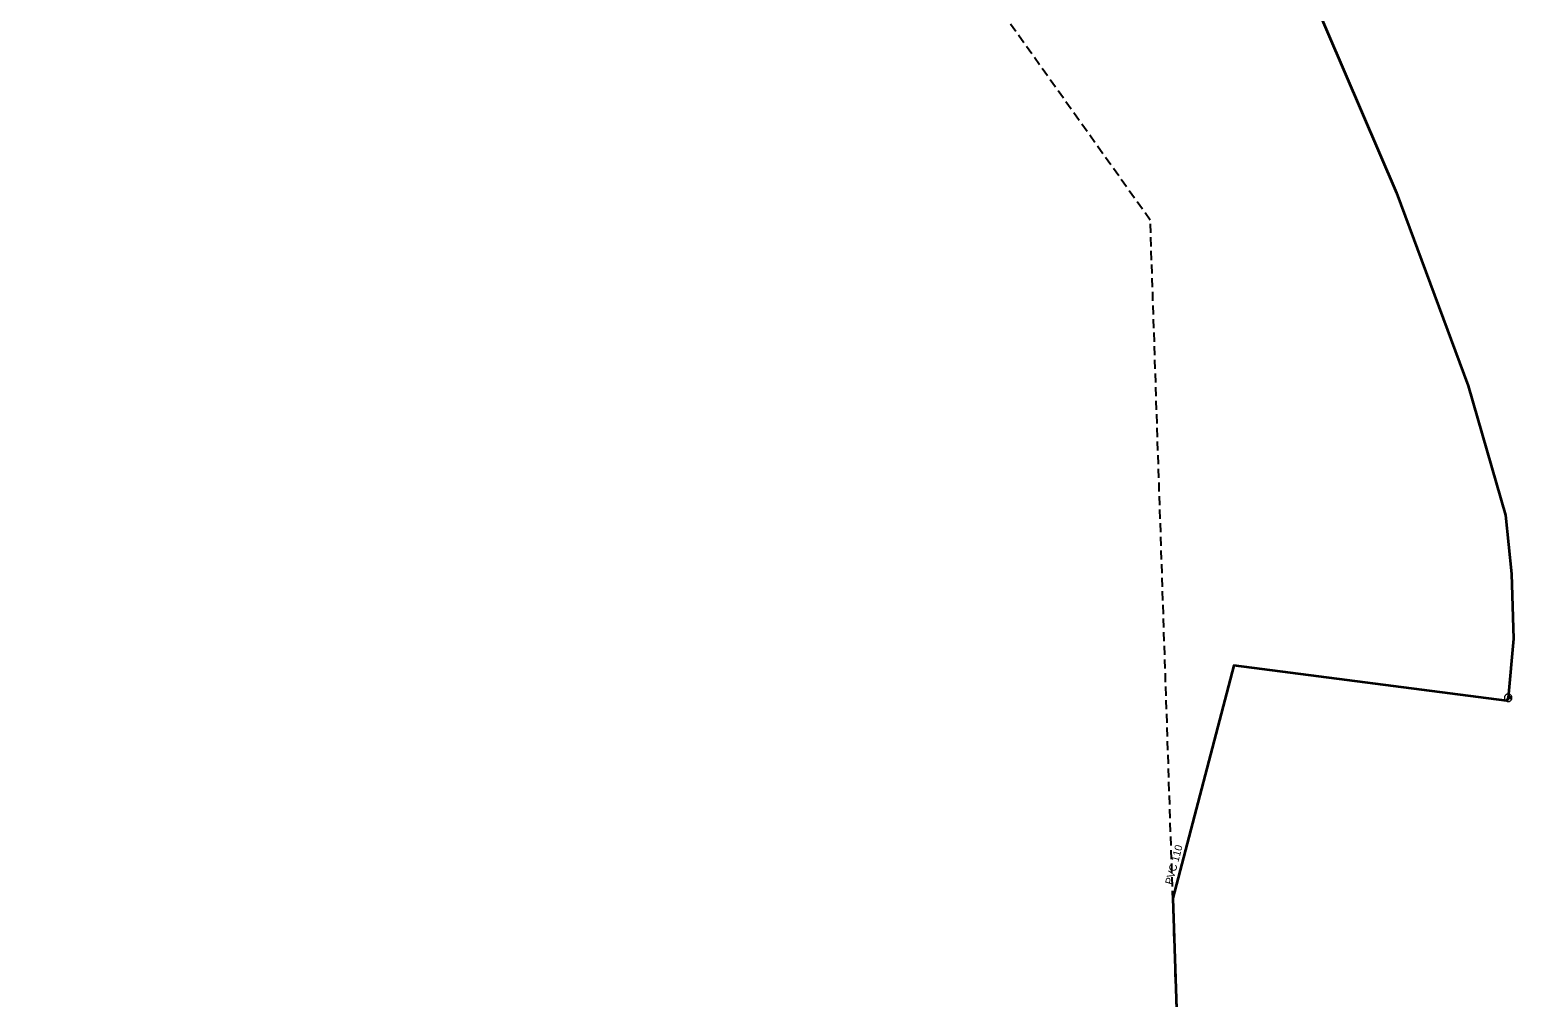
# Model space of a CAD drawing. Extents: x -724334 to -723692, y -972150 to -970648.
# Drawn here: x -724012.8 to -723813.6, y -971527.1 to -971399.3 of the extents above; entities that cross this region are included whole.
import ezdxf

# ---------------------------------------------------------------- set-up
doc = ezdxf.new("R2010")
doc.units = 0
doc.header["$LTSCALE"] = 0.4
doc.linetypes.add('MEDIUM_DASHED', pattern=[4.5, 3, -1.5])
for name, color, linetype, lineweight in [('1', 7, 'Continuous', 25), ('14', 7, 'Continuous', 25), ('17', 7, 'Continuous', 35), ('47', 7, 'Continuous', 13), ('9', 7, 'Continuous', 13)]:
    doc.layers.add(name, color=color, linetype=linetype, lineweight=lineweight)

msp = doc.modelspace()

# ---------------------------------------------------------------- linework, layer by layer
at = {"layer": '1', "linetype": 'MEDIUM_DASHED'}
msp.add_lwpolyline([(-723848.074, -970648.428), (-723714.095, -970720.999), (-724065.788, -971064.318), (-723792.249, -971201.088), (-723702.93, -971508.122), (-723691.766, -972150.101), (-723842.491, -972097.068), (-723864.821, -971424.385), (-723982.052, -971259.703), (-724333.745, -971117.352)], close=True, dxfattribs=at)
at = {"layer": '14', "lineweight": 13}
msp.add_line((-723817.559, -971487.479), (-723817.31, -971487.459), dxfattribs=at)
at = {"layer": '17'}
for points in [[(-723897.32, -971301.379), (-723897.12, -971301.809), (-723878.899, -971335.289), (-723856.64, -971370.239), (-723846.059, -971388.75), (-723832.309, -971420.76), (-723822.829, -971446.28), (-723817.91, -971463.35), (-723817.129, -971471.1), (-723816.85, -971479.71), (-723817.559, -971487.479)], [(-723817.559, -971487.479), (-723817.73, -971487.899), (-723853.789, -971483.199), (-723861.847, -971513.967), (-723856.42, -971677.472)]]:
    msp.add_lwpolyline(points, dxfattribs=at)
at = {"layer": '47'}
for points in [[(-723817.537, -971487.978), (-723817.485, -971487.973), (-723817.434, -971487.963), (-723817.384, -971487.947), (-723817.336, -971487.926), (-723817.29, -971487.9), (-723817.248, -971487.87), (-723817.209, -971487.835), (-723817.174, -971487.796), (-723817.142, -971487.755), (-723817.115, -971487.71), (-723817.093, -971487.662), (-723817.077, -971487.612), (-723817.066, -971487.562), (-723817.06, -971487.509), (-723817.059, -971487.457), (-723817.064, -971487.405), (-723817.074, -971487.354), (-723817.091, -971487.303), (-723817.111, -971487.256), (-723817.137, -971487.21), (-723817.167, -971487.168), (-723817.202, -971487.128), (-723817.241, -971487.093), (-723817.282, -971487.061), (-723817.327, -971487.035), (-723817.375, -971487.013), (-723817.425, -971486.996), (-723817.475, -971486.986), (-723817.528, -971486.98), (-723817.58, -971486.979), (-723817.632, -971486.984), (-723817.683, -971486.994), (-723817.734, -971487.01), (-723817.781, -971487.031), (-723817.827, -971487.057), (-723817.869, -971487.086), (-723817.909, -971487.121), (-723817.944, -971487.16), (-723817.976, -971487.202), (-723818.002, -971487.247), (-723818.024, -971487.295), (-723818.041, -971487.344), (-723818.051, -971487.395), (-723818.057, -971487.448), (-723818.058, -971487.5), (-723818.053, -971487.552), (-723818.043, -971487.603), (-723818.028, -971487.653), (-723818.006, -971487.701), (-723817.98, -971487.747), (-723817.951, -971487.789), (-723817.916, -971487.828), (-723817.877, -971487.863), (-723817.835, -971487.895), (-723817.79, -971487.922), (-723817.742, -971487.944), (-723817.693, -971487.96), (-723817.642, -971487.971), (-723817.589, -971487.977)], [(-723817.555, -971487.56), (-723817.546, -971487.56), (-723817.538, -971487.558), (-723817.53, -971487.555), (-723817.522, -971487.552), (-723817.515, -971487.548), (-723817.508, -971487.542), (-723817.501, -971487.537), (-723817.495, -971487.531), (-723817.491, -971487.524), (-723817.486, -971487.516), (-723817.482, -971487.508), (-723817.48, -971487.5), (-723817.478, -971487.492), (-723817.476, -971487.484), (-723817.477, -971487.475), (-723817.477, -971487.466), (-723817.479, -971487.458), (-723817.482, -971487.45), (-723817.485, -971487.442), (-723817.489, -971487.435), (-723817.495, -971487.428), (-723817.5, -971487.421), (-723817.506, -971487.415), (-723817.513, -971487.41), (-723817.521, -971487.406), (-723817.529, -971487.402), (-723817.537, -971487.4), (-723817.545, -971487.398), (-723817.553, -971487.396), (-723817.562, -971487.397), (-723817.571, -971487.397), (-723817.579, -971487.399), (-723817.587, -971487.402), (-723817.595, -971487.405), (-723817.602, -971487.409), (-723817.609, -971487.414), (-723817.616, -971487.42), (-723817.622, -971487.426), (-723817.627, -971487.433), (-723817.631, -971487.441), (-723817.635, -971487.449), (-723817.637, -971487.457), (-723817.639, -971487.465), (-723817.641, -971487.473), (-723817.64, -971487.482), (-723817.64, -971487.491), (-723817.638, -971487.499), (-723817.635, -971487.507), (-723817.632, -971487.515), (-723817.628, -971487.522), (-723817.623, -971487.529), (-723817.617, -971487.536), (-723817.611, -971487.542), (-723817.604, -971487.546), (-723817.596, -971487.551), (-723817.588, -971487.555), (-723817.58, -971487.557), (-723817.572, -971487.559), (-723817.564, -971487.561)]]:
    msp.add_lwpolyline(points, close=True, dxfattribs=at)
at = {"layer": '9'}
for points in [[(-723817.436, -971487.459), (-723817.436, -971487.472), (-723817.434, -971487.485), (-723817.431, -971487.498), (-723817.426, -971487.51), (-723817.42, -971487.522), (-723817.413, -971487.533), (-723817.405, -971487.543), (-723817.395, -971487.553), (-723817.385, -971487.561), (-723817.374, -971487.568), (-723817.362, -971487.574), (-723817.35, -971487.579), (-723817.337, -971487.582), (-723817.324, -971487.584), (-723817.311, -971487.586), (-723817.298, -971487.585), (-723817.285, -971487.583), (-723817.272, -971487.58), (-723817.26, -971487.575), (-723817.248, -971487.569), (-723817.237, -971487.562), (-723817.227, -971487.554), (-723817.217, -971487.544), (-723817.209, -971487.534), (-723817.202, -971487.523), (-723817.196, -971487.511), (-723817.191, -971487.499), (-723817.188, -971487.486), (-723817.186, -971487.473), (-723817.184, -971487.46), (-723817.185, -971487.447), (-723817.187, -971487.434), (-723817.19, -971487.421), (-723817.195, -971487.409), (-723817.201, -971487.397), (-723817.208, -971487.386), (-723817.216, -971487.376), (-723817.226, -971487.366), (-723817.236, -971487.358), (-723817.247, -971487.351), (-723817.259, -971487.345), (-723817.271, -971487.34), (-723817.284, -971487.337), (-723817.297, -971487.335), (-723817.31, -971487.334), (-723817.323, -971487.334), (-723817.336, -971487.336), (-723817.349, -971487.339), (-723817.361, -971487.344), (-723817.373, -971487.35), (-723817.384, -971487.357), (-723817.394, -971487.365), (-723817.404, -971487.375), (-723817.412, -971487.385), (-723817.419, -971487.396), (-723817.425, -971487.408), (-723817.43, -971487.42), (-723817.433, -971487.433), (-723817.435, -971487.446)], [(-723817.416, -971487.459), (-723817.417, -971487.47), (-723817.415, -971487.481), (-723817.412, -971487.492), (-723817.408, -971487.502), (-723817.403, -971487.512), (-723817.397, -971487.521), (-723817.39, -971487.53), (-723817.382, -971487.538), (-723817.373, -971487.545), (-723817.364, -971487.551), (-723817.354, -971487.556), (-723817.344, -971487.56), (-723817.333, -971487.563), (-723817.322, -971487.566), (-723817.311, -971487.566), (-723817.3, -971487.566), (-723817.289, -971487.564), (-723817.278, -971487.561), (-723817.268, -971487.557), (-723817.258, -971487.552), (-723817.249, -971487.546), (-723817.24, -971487.539), (-723817.232, -971487.531), (-723817.225, -971487.522), (-723817.219, -971487.513), (-723817.214, -971487.503), (-723817.21, -971487.493), (-723817.207, -971487.482), (-723817.205, -971487.471), (-723817.204, -971487.46), (-723817.204, -971487.449), (-723817.206, -971487.438), (-723817.209, -971487.427), (-723817.213, -971487.417), (-723817.218, -971487.407), (-723817.224, -971487.398), (-723817.231, -971487.389), (-723817.239, -971487.381), (-723817.248, -971487.374), (-723817.257, -971487.368), (-723817.267, -971487.363), (-723817.277, -971487.359), (-723817.288, -971487.356), (-723817.299, -971487.354), (-723817.31, -971487.354), (-723817.321, -971487.353), (-723817.332, -971487.355), (-723817.343, -971487.358), (-723817.353, -971487.362), (-723817.363, -971487.367), (-723817.372, -971487.373), (-723817.381, -971487.38), (-723817.389, -971487.388), (-723817.396, -971487.397), (-723817.402, -971487.406), (-723817.407, -971487.416), (-723817.411, -971487.426), (-723817.414, -971487.437), (-723817.416, -971487.448)], [(-723817.397, -971487.459), (-723817.397, -971487.468), (-723817.396, -971487.477), (-723817.393, -971487.486), (-723817.39, -971487.494), (-723817.386, -971487.502), (-723817.381, -971487.51), (-723817.375, -971487.517), (-723817.369, -971487.523), (-723817.362, -971487.529), (-723817.354, -971487.534), (-723817.346, -971487.538), (-723817.338, -971487.541), (-723817.329, -971487.544), (-723817.32, -971487.545), (-723817.311, -971487.547), (-723817.302, -971487.546), (-723817.293, -971487.545), (-723817.284, -971487.542), (-723817.276, -971487.539), (-723817.268, -971487.535), (-723817.26, -971487.53), (-723817.253, -971487.524), (-723817.247, -971487.518), (-723817.241, -971487.511), (-723817.236, -971487.503), (-723817.232, -971487.495), (-723817.229, -971487.487), (-723817.226, -971487.478), (-723817.225, -971487.469), (-723817.223, -971487.46), (-723817.224, -971487.451), (-723817.225, -971487.442), (-723817.228, -971487.433), (-723817.231, -971487.425), (-723817.235, -971487.417), (-723817.24, -971487.409), (-723817.246, -971487.402), (-723817.252, -971487.396), (-723817.259, -971487.39), (-723817.267, -971487.385), (-723817.275, -971487.381), (-723817.283, -971487.378), (-723817.292, -971487.375), (-723817.301, -971487.374), (-723817.31, -971487.373), (-723817.319, -971487.373), (-723817.328, -971487.374), (-723817.337, -971487.377), (-723817.345, -971487.38), (-723817.353, -971487.384), (-723817.361, -971487.389), (-723817.368, -971487.395), (-723817.374, -971487.401), (-723817.38, -971487.408), (-723817.385, -971487.416), (-723817.389, -971487.424), (-723817.392, -971487.432), (-723817.395, -971487.441), (-723817.396, -971487.45)], [(-723817.377, -971487.459), (-723817.377, -971487.466), (-723817.376, -971487.473), (-723817.375, -971487.48), (-723817.372, -971487.486), (-723817.369, -971487.492), (-723817.365, -971487.498), (-723817.361, -971487.504), (-723817.356, -971487.509), (-723817.35, -971487.513), (-723817.344, -971487.517), (-723817.338, -971487.52), (-723817.332, -971487.523), (-723817.325, -971487.524), (-723817.318, -971487.527), (-723817.311, -971487.527), (-723817.304, -971487.527), (-723817.297, -971487.525), (-723817.29, -971487.524), (-723817.284, -971487.521), (-723817.277, -971487.518), (-723817.272, -971487.514), (-723817.266, -971487.51), (-723817.261, -971487.505), (-723817.257, -971487.499), (-723817.253, -971487.493), (-723817.25, -971487.487), (-723817.247, -971487.481), (-723817.245, -971487.474), (-723817.244, -971487.467), (-723817.243, -971487.46), (-723817.243, -971487.453), (-723817.244, -971487.446), (-723817.246, -971487.439), (-723817.249, -971487.433), (-723817.252, -971487.426), (-723817.256, -971487.421), (-723817.26, -971487.415), (-723817.265, -971487.41), (-723817.271, -971487.406), (-723817.276, -971487.402), (-723817.283, -971487.399), (-723817.289, -971487.396), (-723817.296, -971487.394), (-723817.303, -971487.393), (-723817.31, -971487.393), (-723817.317, -971487.393), (-723817.324, -971487.393), (-723817.331, -971487.395), (-723817.337, -971487.398), (-723817.343, -971487.401), (-723817.349, -971487.405), (-723817.355, -971487.409), (-723817.36, -971487.414), (-723817.364, -971487.42), (-723817.368, -971487.425), (-723817.371, -971487.432), (-723817.374, -971487.438), (-723817.375, -971487.445), (-723817.377, -971487.452)], [(-723817.357, -971487.459), (-723817.357, -971487.464), (-723817.357, -971487.469), (-723817.356, -971487.474), (-723817.354, -971487.478), (-723817.352, -971487.483), (-723817.349, -971487.487), (-723817.346, -971487.49), (-723817.342, -971487.494), (-723817.339, -971487.497), (-723817.335, -971487.5), (-723817.33, -971487.502), (-723817.326, -971487.504), (-723817.321, -971487.505), (-723817.316, -971487.507), (-723817.311, -971487.507), (-723817.306, -971487.507), (-723817.301, -971487.506), (-723817.296, -971487.505), (-723817.292, -971487.503), (-723817.287, -971487.501), (-723817.283, -971487.498), (-723817.279, -971487.495), (-723817.276, -971487.491), (-723817.273, -971487.488), (-723817.27, -971487.484), (-723817.268, -971487.479), (-723817.266, -971487.475), (-723817.265, -971487.47), (-723817.264, -971487.465), (-723817.263, -971487.46), (-723817.263, -971487.455), (-723817.264, -971487.45), (-723817.265, -971487.445), (-723817.267, -971487.441), (-723817.269, -971487.436), (-723817.272, -971487.432), (-723817.275, -971487.428), (-723817.278, -971487.425), (-723817.282, -971487.422), (-723817.286, -971487.419), (-723817.291, -971487.417), (-723817.295, -971487.415), (-723817.3, -971487.414), (-723817.305, -971487.413), (-723817.31, -971487.413), (-723817.315, -971487.413), (-723817.32, -971487.414), (-723817.325, -971487.414), (-723817.329, -971487.416), (-723817.334, -971487.418), (-723817.338, -971487.421), (-723817.341, -971487.424), (-723817.345, -971487.427), (-723817.348, -971487.431), (-723817.351, -971487.435), (-723817.353, -971487.44), (-723817.355, -971487.444), (-723817.356, -971487.449), (-723817.357, -971487.454)], [(-723817.337, -971487.459), (-723817.337, -971487.462), (-723817.338, -971487.465), (-723817.337, -971487.467), (-723817.336, -971487.47), (-723817.335, -971487.473), (-723817.333, -971487.475), (-723817.331, -971487.477), (-723817.329, -971487.479), (-723817.327, -971487.481), (-723817.325, -971487.483), (-723817.322, -971487.485), (-723817.319, -971487.486), (-723817.317, -971487.486), (-723817.314, -971487.487), (-723817.311, -971487.487), (-723817.308, -971487.487), (-723817.305, -971487.487), (-723817.302, -971487.486), (-723817.3, -971487.485), (-723817.297, -971487.484), (-723817.295, -971487.482), (-723817.292, -971487.48), (-723817.29, -971487.478), (-723817.289, -971487.476), (-723817.287, -971487.474), (-723817.286, -971487.471), (-723817.284, -971487.468), (-723817.284, -971487.466), (-723817.283, -971487.463), (-723817.282, -971487.46), (-723817.283, -971487.457), (-723817.283, -971487.454), (-723817.284, -971487.451), (-723817.285, -971487.449), (-723817.286, -971487.446), (-723817.288, -971487.444), (-723817.289, -971487.441), (-723817.291, -971487.439), (-723817.294, -971487.438), (-723817.296, -971487.436), (-723817.299, -971487.435), (-723817.301, -971487.434), (-723817.304, -971487.433), (-723817.307, -971487.433), (-723817.31, -971487.432), (-723817.313, -971487.433), (-723817.316, -971487.432), (-723817.318, -971487.434), (-723817.321, -971487.434), (-723817.324, -971487.435), (-723817.326, -971487.437), (-723817.328, -971487.438), (-723817.33, -971487.44), (-723817.332, -971487.443), (-723817.334, -971487.445), (-723817.335, -971487.448), (-723817.336, -971487.45), (-723817.337, -971487.453), (-723817.337, -971487.456)], [(-723817.318, -971487.459), (-723817.318, -971487.461), (-723817.318, -971487.461), (-723817.317, -971487.461), (-723817.317, -971487.463), (-723817.318, -971487.464), (-723817.316, -971487.464), (-723817.316, -971487.464), (-723817.316, -971487.466), (-723817.316, -971487.466), (-723817.315, -971487.467), (-723817.313, -971487.467), (-723817.313, -971487.467), (-723817.313, -971487.468), (-723817.311, -971487.468), (-723817.311, -971487.468), (-723817.31, -971487.468), (-723817.309, -971487.468), (-723817.309, -971487.467), (-723817.308, -971487.467), (-723817.306, -971487.467), (-723817.306, -971487.466), (-723817.306, -971487.466), (-723817.305, -971487.465), (-723817.305, -971487.465), (-723817.303, -971487.464), (-723817.303, -971487.463), (-723817.302, -971487.462), (-723817.302, -971487.462), (-723817.302, -971487.461), (-723817.302, -971487.46), (-723817.302, -971487.459), (-723817.302, -971487.458), (-723817.302, -971487.458), (-723817.303, -971487.457), (-723817.303, -971487.456), (-723817.304, -971487.455), (-723817.304, -971487.455), (-723817.305, -971487.454), (-723817.305, -971487.454), (-723817.306, -971487.453), (-723817.307, -971487.453), (-723817.308, -971487.452), (-723817.308, -971487.452), (-723817.309, -971487.452), (-723817.31, -971487.452), (-723817.311, -971487.452), (-723817.312, -971487.452), (-723817.312, -971487.452), (-723817.313, -971487.453), (-723817.314, -971487.452), (-723817.315, -971487.454), (-723817.315, -971487.454), (-723817.316, -971487.454), (-723817.316, -971487.454), (-723817.317, -971487.456), (-723817.317, -971487.457), (-723817.317, -971487.458), (-723817.318, -971487.458), (-723817.318, -971487.459)]]:
    msp.add_lwpolyline(points, close=True, dxfattribs=at)

# ---------------------------------------------------------------- texts
at = {"layer": '1'}
msp.add_text('PVC 110 ', height=1, rotation=75, dxfattribs=at).set_placement((-723861.928, -971512.237))

doc.saveas('drawing.dxf')
